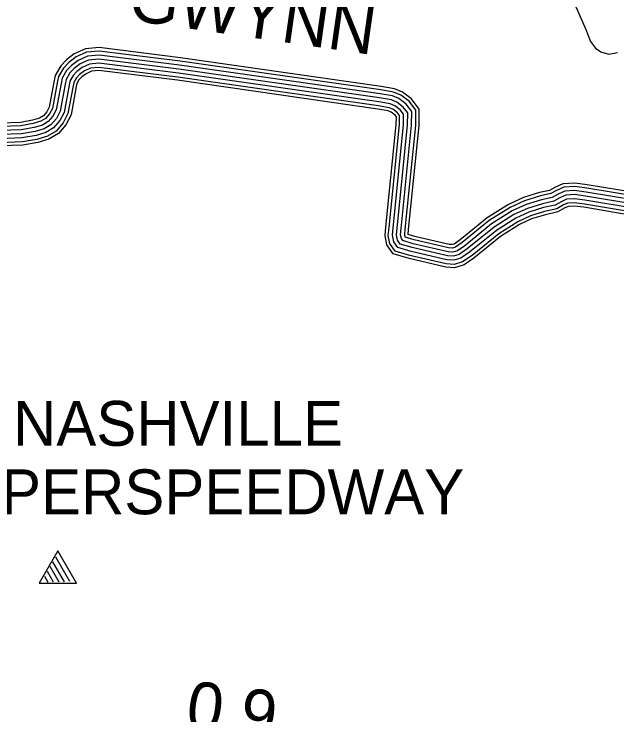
# Model space of a CAD drawing. Extents: x 1788175 to 1969470, y 584502 to 738744.
# Drawn here: x 1846751 to 1851363, y 621579 to 626936 of the extents above; entities that cross this region are included whole.
import ezdxf

# ---------------------------------------------------------------- set-up
doc = ezdxf.new("R2010")
doc.units = 0
for name, color, linetype in [('DESIGN - ROW - Right-of-Way and Easement Labels', 7, 'Continuous'), ('DESIGN - TRAFFIC CONTROL PERMANENT - Signalization', 7, 'Continuous'), ('DESIGN - TRANSPORTATION - Text', 7, 'Continuous'), ('DESIGN - UTILITIES - Cable (Underground) with Text', 7, 'Continuous'), ('SURVEY - TRANSPORTATION - Roads', 7, 'Continuous')]:
    doc.layers.add(name, color=color, linetype=linetype)

msp = doc.modelspace()

# ---------------------------------------------------------------- linework, layer by layer
at = {"layer": 'DESIGN - TRANSPORTATION - Text'}
msp.add_lwpolyline([(1850859.3, 627410.7), (1850967.6, 627168.1), (1851064.2, 626957.5), (1851123.9, 626816.4), (1851161, 626727), (1851197.6, 626675.5), (1851239.9, 626648.1), (1851300, 626629), (1851365.8, 626641.9)], dxfattribs=at)
at = {"layer": 'DESIGN - UTILITIES - Cable (Underground) with Text'}
for p, q in [((1847086.2, 622833.1), (1846943.7, 622586.2)), ((1847228.8, 622586.2), (1847086.2, 622833.1)), ((1847137.8, 622595.9), (1847048.8, 622750.1)), ((1847177.9, 622600.3), (1847071.1, 622785.4)), ((1847096.1, 622594.3), (1847027.3, 622713.4)), ((1847053.6, 622594), (1847006.6, 622675.3)), ((1847011.9, 622592.3), (1846986, 622637.2)), ((1846943.7, 622586.2), (1847228.8, 622586.2))]:
    msp.add_line(p, q, dxfattribs=at)
at = {"layer": 'SURVEY - TRANSPORTATION - Roads'}
for points in [[(1851508.3, 625568.3), (1851135.1, 625631.7), (1851040.6, 625643.8), (1850949.4, 625637.2), (1850887.9, 625611), (1850847.3, 625588.3), (1850770.8, 625571.2), (1850646.6, 625532.9), (1850532.9, 625480.6), (1850371, 625378.7), (1850163.8, 625210.5), (1850117, 625177.9), (1850102.3, 625173.6), (1850078.6, 625175.3), (1849817.5, 625235.4), (1849764.9, 625251), (1849764.8, 625251.7), (1849768.7, 625290), (1849848.9, 626082.9), (1849850, 626208.9), (1849790.3, 626287.5), (1849723.4, 626339.1), (1849661.1, 626364.8), (1849560.2, 626381.4), (1848024, 626602.1), (1847401.8, 626678.8), (1847297.9, 626669.6), (1847211.7, 626630.4), (1847153.2, 626585.9), (1847107.6, 626539), (1847065.7, 626467), (1847055.1, 626415.9), (1847019.9, 626223.3), (1847001.3, 626187.5), (1846975.9, 626157.6), (1846946.1, 626139.9), (1846892.1, 626123.6), (1846799.5, 626108), (1846650.2, 626102.3)], [(1851498, 625512.6), (1851126.7, 625575.6), (1851039, 625586.9), (1850962.9, 625581.3), (1850912.9, 625560), (1850867.8, 625534.8), (1850785.4, 625516.3), (1850666.9, 625479.8), (1850560, 625430.6), (1850404.1, 625332.5), (1850198, 625165.2), (1850141.8, 625126), (1850108.3, 625116.3), (1850070.2, 625119.1), (1849803, 625180.5), (1849724.3, 625203.9), (1849713.6, 625219.5), (1849707.4, 625248.6), (1849712.3, 625295.8), (1849792.2, 626086), (1849793.1, 626190), (1849749.7, 626247.2), (1849694.8, 626289.6), (1849645.5, 626309.9), (1849551.6, 626325.3), (1848016.5, 626545.9), (1847400.8, 626621.8), (1847312.5, 626613.9), (1847241, 626581.4), (1847190.9, 626543.3), (1847153.1, 626504.5), (1847119.4, 626446.4), (1847110.7, 626405), (1847074.2, 626204.8), (1847048.7, 626155.7), (1847013, 626113.7), (1846969.1, 626087.6), (1846905, 626068.3), (1846805.3, 626051.5), (1846648, 626045.4)], [(1851503.7, 625543.1), (1851131.3, 625606.2), (1851039.8, 625618), (1850955.5, 625611.9), (1850899.2, 625587.9), (1850856.6, 625564), (1850777.4, 625546.3), (1850655.8, 625508.8), (1850545.2, 625458), (1850386, 625357.7), (1850179.3, 625190), (1850128.2, 625154.3), (1850105, 625147.6), (1850074.8, 625149.8), (1849810.9, 625210.5), (1849743.7, 625230.5), (1849742.7, 625231.9), (1849738.8, 625250.2), (1849743.1, 625292.6), (1849823.2, 626084.3), (1849824.2, 626200.3), (1849771.9, 626269.3), (1849710.4, 626316.7), (1849654, 626339.9), (1849556.3, 626355.9), (1848020.6, 626576.6), (1847401.4, 626653), (1847304.5, 626644.3), (1847225, 626608.2), (1847170.3, 626566.6), (1847128.2, 626523.3), (1847090, 626457.7), (1847080.3, 626411), (1847044.5, 626214.9), (1847022.8, 626173.1), (1846992.7, 626137.7), (1846956.5, 626116.2), (1846898, 626098.5), (1846802.1, 626082.4), (1846649.2, 626076.5)], [(1851486.8, 625451.6), (1851117.6, 625514.2), (1851037.3, 625524.6), (1850977.7, 625520.2), (1850940.3, 625504.3), (1850890.2, 625476.3), (1850801.3, 625456.4), (1850689.1, 625421.7), (1850589.6, 625376), (1850440.3, 625282), (1850235.3, 625115.7), (1850168.8, 625069.2), (1850114.8, 625053.7), (1850060.9, 625057.6), (1849787.3, 625120.6), (1849685.6, 625150.7), (1849655.5, 625194.5), (1849644.8, 625245.2), (1849650.6, 625302.1), (1849730.2, 626089.4), (1849731, 626169.4), (1849705.3, 626203.2), (1849663.5, 626235.4), (1849628.4, 626249.9), (1849542.2, 626264), (1848008.3, 626484.5), (1847399.8, 626559.5), (1847328.5, 626553.1), (1847273, 626527.9), (1847232.1, 626496.8), (1847202.9, 626466.7), (1847178, 626423.9), (1847171.6, 626393.1), (1847133.5, 626184.5), (1847100.5, 626120.9), (1847053.5, 626065.7), (1846994.3, 626030.4), (1846919.2, 626007.8), (1846811.7, 625989.7), (1846645.6, 625983.3)], [(1851492.4, 625482.1), (1851122.1, 625544.9), (1851038.1, 625555.7), (1850970.3, 625550.8), (1850926.6, 625532.2), (1850879, 625505.5), (1850793.4, 625486.3), (1850678, 625450.7), (1850574.8, 625403.3), (1850422.2, 625307.2), (1850216.6, 625140.4), (1850155.3, 625097.6), (1850111.5, 625085), (1850065.5, 625088.3), (1849795.1, 625150.6), (1849704.9, 625177.3), (1849684.6, 625207), (1849676.1, 625246.9), (1849681.4, 625298.9), (1849761.2, 626087.7), (1849762, 626179.7), (1849727.5, 626225.2), (1849679.1, 626262.5), (1849637, 626279.9), (1849546.9, 626294.7), (1848012.4, 626515.2), (1847400.3, 626590.6), (1847320.5, 626583.5), (1847257, 626554.7), (1847211.5, 626520), (1847178, 626485.6), (1847148.7, 626435.2), (1847141.1, 626399.1), (1847103.8, 626194.7), (1847074.6, 626138.3), (1847033.3, 626089.7), (1846981.7, 626059), (1846912.1, 626038), (1846808.5, 626020.6), (1846646.8, 626014.4)], [(1851492.4, 625482.1), (1851122.1, 625544.9), (1851038.1, 625555.7), (1850970.3, 625550.8), (1850926.6, 625532.2), (1850879, 625505.5), (1850793.4, 625486.3), (1850678, 625450.7), (1850574.8, 625403.3), (1850422.2, 625307.2), (1850216.6, 625140.4), (1850155.3, 625097.6), (1850111.5, 625085), (1850065.5, 625088.3), (1849795.1, 625150.6), (1849704.9, 625177.3), (1849684.6, 625207), (1849676.1, 625246.9), (1849681.4, 625298.9), (1849761.2, 626087.7), (1849762, 626179.7), (1849727.5, 626225.2), (1849679.1, 626262.5), (1849637, 626279.9), (1849546.9, 626294.7), (1848012.4, 626515.2), (1847400.3, 626590.6), (1847320.5, 626583.5), (1847257, 626554.7), (1847211.5, 626520), (1847178, 626485.6), (1847148.7, 626435.2), (1847141.1, 626399.1), (1847103.8, 626194.7), (1847074.6, 626138.3), (1847033.3, 626089.7), (1846981.7, 626059), (1846912.1, 626038), (1846808.5, 626020.6), (1846646.8, 626014.4)], [(1851476.6, 625396.8), (1851109.3, 625459.1), (1851035.7, 625468.6), (1850991, 625465.3), (1850964.9, 625454.2), (1850910.3, 625423.7), (1850815.7, 625402.5), (1850709, 625369.6), (1850616.2, 625326.9), (1850472.8, 625236.6), (1850268.9, 625071.1), (1850193.1, 625018.3), (1850120.6, 624997.4), (1850052.6, 625002.3), (1849773.1, 625066.6), (1849650.8, 625102.9), (1849603.3, 625172.1), (1849588.4, 625242.1), (1849595.1, 625307.7), (1849674.5, 626092.5), (1849675.1, 626150.9), (1849665.4, 626163.6), (1849635.3, 626186.8), (1849613.1, 626195.9), (1849533.7, 626208.9), (1848000.9, 626429.2), (1847398.8, 626503.4), (1847342.9, 626498.5), (1847301.7, 626479.7), (1847269.2, 626454.9), (1847247.6, 626432.8), (1847230.7, 626403.7), (1847226.3, 626382.4), (1847186.8, 626166.3), (1847147, 626089.6), (1847090, 626022.6), (1847017, 625979), (1846931.9, 625953.4), (1846817.4, 625934.2), (1846643.4, 625927.4)], [(1851481.1, 625421.1), (1851113, 625483.6), (1851036.4, 625493.4), (1850985.1, 625489.7), (1850954, 625476.4), (1850901.4, 625447), (1850809.3, 625426.4), (1850700.2, 625392.7), (1850604.4, 625348.7), (1850458.4, 625256.7), (1850254, 625090.9), (1850182.3, 625040.9), (1850118, 625022.3), (1850056.3, 625026.9), (1849779.4, 625090.6), (1849666.2, 625124.1), (1849626.5, 625182.1), (1849613.4, 625243.5), (1849619.7, 625305.2), (1849699.2, 626091.1), (1849699.9, 626159.1), (1849683.1, 626181.1), (1849647.8, 626208.4), (1849619.9, 626219.9), (1849537.5, 626233.4), (1848004.2, 626453.7), (1847399.3, 626528.3), (1847336.6, 626522.7), (1847289, 626501.1), (1847252.7, 626473.5), (1847227.7, 626447.8), (1847207.3, 626412.7), (1847202, 626387.2), (1847163.1, 626174.4), (1847126.4, 626103.5), (1847073.8, 626041.7), (1847006.9, 626001.8), (1846926.2, 625977.5), (1846814.8, 625958.8), (1846644.4, 625952.2)]]:
    msp.add_lwpolyline(points, dxfattribs=at)

# ---------------------------------------------------------------- texts
at = {"layer": 'DESIGN - ROW - Right-of-Way and Easement Labels'}
msp.add_text('GWYNN', height=370, rotation=351.8218, dxfattribs=at).set_placement((1847612.8, 626892.9))
at = {"layer": 'DESIGN - TRAFFIC CONTROL PERMANENT - Signalization'}
msp.add_text('0.9', height=369.6, rotation=352.4199, dxfattribs=at).set_placement((1848054.3, 621477.4))
at = {"layer": 'DESIGN - UTILITIES - Cable (Underground) with Text'}
for s, height, p in [('NASHVILLE', 343, (1846743.1, 623636.2)), ('SUPERSPEEDWAY', 342.999, (1846014.3, 623112.9))]:
    msp.add_text(s, height=height, dxfattribs=at).set_placement(p)

doc.saveas('drawing.dxf')
